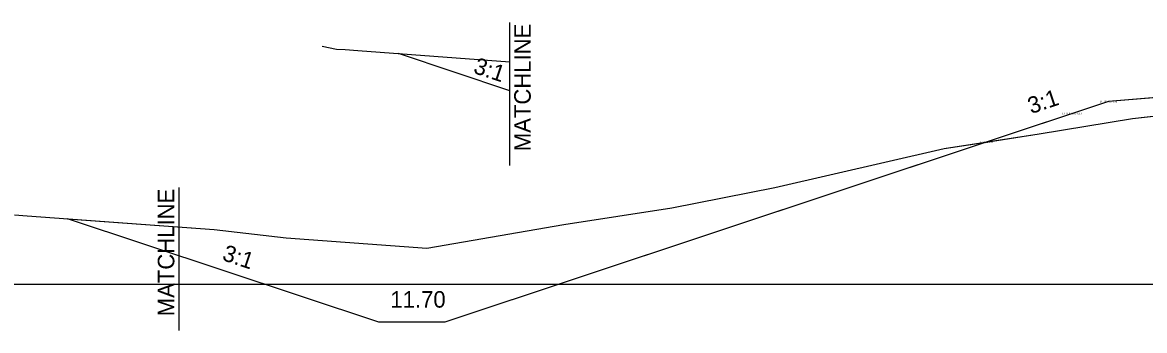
# Model space of a CAD drawing. Extents: x 2207892 to 2209721, y 61220 to 65449.
# Drawn here: x 2208013.7 to 2208081.6, y 61904.5 to 61923.2 of the extents above; entities that cross this region are included whole.
import ezdxf

# ---------------------------------------------------------------- set-up
doc = ezdxf.new("R2010")
doc.units = 0
for name, color, linetype in [('Exist DTM Breakline Cogo Comment', 7, 'Continuous'), ('Exist DTM Breakline Cogo Elevation', 7, 'Continuous'), ('Exist DTM Breakline Underwater Cogo Comment', 7, 'Continuous'), ('Exist DTM Ridgeline Cogo Comment', 7, 'Continuous'), ('Exist Hydro Stream or Body of Water Cogo Elevation', 7, 'Continuous'), ('Exist Roads EOP Other Cogo Elevation', 7, 'Continuous'), ('Exist Roads EOP Other Cogo Number', 7, 'Continuous'), ('Exist Structure Minor Head and End Wall Cogo Point CELL', 7, 'Continuous')]:
    doc.layers.add(name, color=color, linetype=linetype)

msp = doc.modelspace()

# ---------------------------------------------------------------- linework, layer by layer
at = {"layer": 'Exist DTM Breakline Cogo Comment'}
for points in [[(2208080.833, 61917.347), (2208085.378, 61917.866), (2208083.857, 61917.828), (2208083.009, 61918.676), (2208079.382, 61918.386), (2208071.987, 61915.921), (2208075.187, 61916.417)], [(2208059.203, 61913.168), (2208069.446, 61915.528), (2208071.987, 61915.921), (2208039.255, 61905.01), (2208035.255, 61905.01), (2208016.44, 61911.282), (2208025.308, 61910.622), (2208029.654, 61910.125), (2208038.159, 61909.492), (2208046.438, 61910.927), (2208052.975, 61911.936)]]:
    msp.add_lwpolyline(points, close=True, dxfattribs=at)
at = {"layer": 'Exist DTM Breakline Cogo Elevation'}
for p, q in [((2208043.174, 61914.502), (2208043.174, 61923.174)), ((2208043.174, 61919.037), (2208036.44, 61921.282)), ((2208023.174, 61904.502), (2208023.174, 61913.174))]:
    msp.add_line(p, q, dxfattribs=at)
msp.add_lwpolyline([(2208031.825, 61921.738), (2208032.699, 61921.561), (2208033.22, 61921.525), (2208033.987, 61921.464), (2208043.174, 61920.781)], dxfattribs=at)
at = {"layer": 'Exist Hydro Stream or Body of Water Cogo Elevation'}
for p, q in [((2208085.382, 61918.866), (2208079.382, 61918.386)), ((2208079.382, 61918.386), (2208039.255, 61905.01)), ((2208035.255, 61905.01), (2208016.44, 61911.282)), ((2208039.255, 61905.01), (2208035.255, 61905.01))]:
    msp.add_line(p, q, dxfattribs=at)
at = {"layer": 'Exist Roads EOP Other Cogo Elevation'}
msp.add_lwpolyline([(2208013.22, 61911.525), (2208013.987, 61911.464), (2208025.308, 61910.622), (2208029.654, 61910.125), (2208038.159, 61909.492), (2208046.438, 61910.927), (2208052.975, 61911.936), (2208059.203, 61913.168), (2208069.446, 61915.528), (2208075.187, 61916.417), (2208080.833, 61917.347), (2208087.392, 61918.096)], dxfattribs=at)
at = {"layer": 'Exist Roads EOP Other Cogo Number'}
msp.add_line((2207918.174, 61907.31), (2208118.174, 61907.31), dxfattribs=at)

# ---------------------------------------------------------------- texts
at = {"layer": 'Exist DTM Breakline Cogo Elevation'}
for p in [(2208044.442, 61915.37), (2208022.89, 61905.37)]:
    msp.add_text('MATCHLINE', height=1, rotation=90, dxfattribs=at).set_placement(p)
at = {"layer": 'Exist DTM Breakline Underwater Cogo Comment'}
for p in [(2208040.917, 61920.126), (2208025.733, 61908.787)]:
    msp.add_text('3:1', height=1, rotation=341.56505, dxfattribs=at).set_placement(p)
msp.add_text('11.70', height=1, dxfattribs=at).set_placement((2208035.951, 61905.893))
at = {"layer": 'Exist DTM Ridgeline Cogo Comment'}
msp.add_text('3:1', height=1, rotation=18.43323, dxfattribs=at).set_placement((2208074.695, 61917.615))
at = {"layer": 'Exist Structure Minor Head and End Wall Cogo Point CELL'}
for s, p in [('LT_GS_OS_CTL', (2208078.851, 61918.336)), ('LT_Sub_OSS_DLT', (2208076.579, 61917.612)), ('LT_Slope_Fill', (2208071.512, 61915.871))]:
    msp.add_text(s, height=0.1, dxfattribs=at).set_placement(p)

doc.saveas('drawing.dxf')
